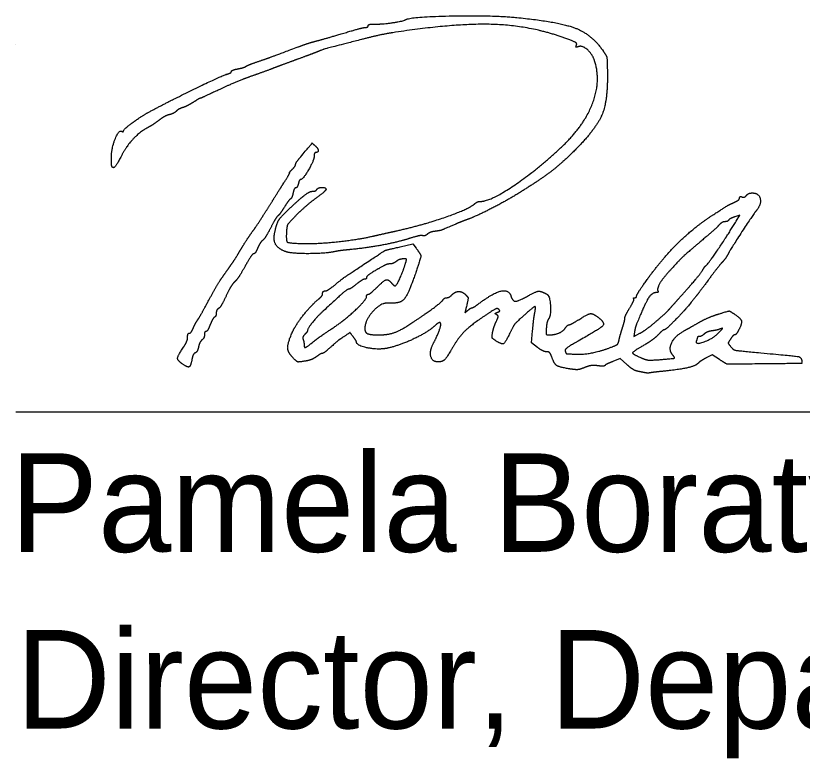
# Model space of a CAD drawing. Extents: x 0 to 40.9, y 0 to 22.
# Drawn here: x 25 to 26.118, y 5.49 to 6.545 of the extents above; entities that cross this region are included whole.
import ezdxf

# ---------------------------------------------------------------- set-up
doc = ezdxf.new("R2010")
doc.units = 0
doc.layers.add('SH_Border', color=7, linetype='Continuous')
doc.layers.add('SH_Cut_Line', color=7, linetype='Continuous')

msp = doc.modelspace()

# ---------------------------------------------------------------- linework, layer by layer
at = {"layer": 'SH_Border'}
for points in [[(26.024, 6.2528), (26.0294, 6.2617), (26.0221, 6.2592)], [(25.5467, 6.2166), (25.5647, 6.2207), (25.5694, 6.2145)], [(25.7417, 6.0738), (25.7334, 6.0802), (25.7348, 6.0972)], [(25.8797, 6.0958), (25.8787, 6.0893), (25.8873, 6.0938)], [(26.0005, 6.0565), (25.9899, 6.0633), (25.9815, 6.0588)], [(25.8686, 6.0495), (25.8595, 6.0578), (25.8489, 6.0537)]]:
    msp.add_lwpolyline(points, dxfattribs=at)
for points in [[(25.5541, 6.5392), (25.5609, 6.5434), (25.6779, 6.5457), (25.7123, 6.5423)], [(25.7123, 6.5423), (25.7716, 6.5365), (25.8191, 6.5182), (25.8349, 6.4951)], [(25.4974, 6.5283), (25.4995, 6.5283), (25.5011, 6.5294), (25.5011, 6.5308)], [(25.5011, 6.5308), (25.5011, 6.5321), (25.5052, 6.5331), (25.5101, 6.533)], [(25.5101, 6.533), (25.5197, 6.5327), (25.5507, 6.5371), (25.5541, 6.5392)], [(25.7848, 6.5116), (25.7343, 6.5305), (25.6263, 6.5345), (25.5359, 6.5208)], [(25.4255, 6.5085), (25.4308, 6.5098), (25.4483, 6.5148), (25.4644, 6.5196)], [(25.4644, 6.5196), (25.4805, 6.5244), (25.4953, 6.5283), (25.4974, 6.5283)], [(25.5359, 6.5208), (25.5267, 6.5193), (25.5067, 6.515), (25.4915, 6.5111)], [(25.4015, 6.5006), (25.4095, 6.5036), (25.4203, 6.5071), (25.4255, 6.5085)], [(25.4915, 6.5111), (25.4405, 6.4979), (25.4363, 6.4966), (25.4255, 6.4923)], [(25.7971, 6.5029), (25.7981, 6.5054), (25.7947, 6.5078), (25.7848, 6.5116)], [(25.3451, 6.48), (25.3598, 6.4851), (25.3663, 6.4875), (25.4015, 6.5006)], [(25.7996, 6.5009), (25.7969, 6.4999), (25.7962, 6.5005), (25.7971, 6.5029)], [(25.8229, 6.4809), (25.8197, 6.4907), (25.8052, 6.503), (25.7996, 6.5009)], [(25.4255, 6.4923), (25.4229, 6.4912), (25.4126, 6.4874), (25.4027, 6.4838)], [(25.8349, 6.4951), (25.8399, 6.4879), (25.8408, 6.4835), (25.8411, 6.4657)], [(25.3271, 6.4729), (25.3285, 6.4739), (25.3366, 6.4771), (25.3451, 6.48)], [(25.4027, 6.4838), (25.3928, 6.4802), (25.3777, 6.4746), (25.3691, 6.4714)], [(25.7774, 6.3597), (25.8084, 6.3892), (25.8322, 6.4527), (25.8229, 6.4809)], [(25.3013, 6.4622), (25.3043, 6.4631), (25.3067, 6.4647), (25.3067, 6.4658)], [(25.3067, 6.4658), (25.3067, 6.4668), (25.3108, 6.4685), (25.3157, 6.4694)], [(25.3157, 6.4694), (25.3207, 6.4703), (25.3258, 6.4719), (25.3271, 6.4729)], [(25.3691, 6.4714), (25.3606, 6.4681), (25.3444, 6.4622), (25.3331, 6.4583)], [(25.8411, 6.4657), (25.8419, 6.4249), (25.8258, 6.3852), (25.7964, 6.3553)], [(25.1891, 6.4079), (25.2194, 6.4241), (25.293, 6.4598), (25.3013, 6.4622)], [(25.3331, 6.4583), (25.3219, 6.4543), (25.3016, 6.4457), (25.2879, 6.4392)], [(25.2879, 6.4392), (25.2743, 6.4328), (25.2626, 6.4275), (25.2621, 6.4275)], [(25.2521, 6.4218), (25.2472, 6.4187), (25.2405, 6.4153), (25.2373, 6.4143)], [(25.2621, 6.4275), (25.2615, 6.4275), (25.257, 6.4249), (25.2521, 6.4218)], [(25.1531, 6.3813), (25.1531, 6.3834), (25.1785, 6.4022), (25.1891, 6.4079)], [(25.2281, 6.4092), (25.2263, 6.4073), (25.2219, 6.4052), (25.2184, 6.4043)], [(25.2373, 6.4143), (25.234, 6.4133), (25.2299, 6.411), (25.2281, 6.4092)], [(25.2035, 6.3962), (25.1989, 6.3927), (25.1918, 6.388), (25.1877, 6.3859)], [(25.2184, 6.4043), (25.2148, 6.4035), (25.2082, 6.3998), (25.2035, 6.3962)], [(25.1877, 6.3859), (25.1772, 6.3806), (25.1573, 6.3597), (25.1511, 6.3476)], [(25.136, 6.3434), (25.1361, 6.3566), (25.1467, 6.3832), (25.1508, 6.3806)], [(25.1508, 6.3806), (25.1521, 6.3798), (25.1531, 6.3801), (25.1531, 6.3813)], [(25.4033, 6.3423), (25.4219, 6.3645), (25.4212, 6.3639), (25.4253, 6.3605)], [(25.4253, 6.3605), (25.4296, 6.3569), (25.4305, 6.3507), (25.4267, 6.3507)], [(25.6607, 6.2811), (25.6748, 6.2811), (25.7429, 6.327), (25.7774, 6.3597)], [(25.7964, 6.3553), (25.7778, 6.3364), (25.7454, 6.3115), (25.7149, 6.2927)], [(25.1373, 6.3297), (25.1365, 6.3305), (25.1359, 6.3366), (25.136, 6.3434)], [(25.1511, 6.3476), (25.1445, 6.3347), (25.1392, 6.3278), (25.1373, 6.3297)], [(25.3979, 6.3337), (25.3979, 6.3349), (25.4004, 6.3388), (25.4033, 6.3423)], [(25.4243, 6.3456), (25.4243, 6.34), (25.4084, 6.3123), (25.4052, 6.3123)], [(25.4267, 6.3507), (25.4254, 6.3507), (25.4243, 6.3484), (25.4243, 6.3456)], [(25.3931, 6.3267), (25.3958, 6.3293), (25.3979, 6.3325), (25.3979, 6.3337)], [(25.3804, 6.3062), (25.3859, 6.3148), (25.39, 6.3219), (25.3894, 6.3219)], [(25.3894, 6.3219), (25.3888, 6.3219), (25.3905, 6.324), (25.3931, 6.3267)], [(25.4052, 6.3123), (25.4041, 6.3123), (25.4026, 6.3096), (25.4018, 6.3063)], [(25.3583, 6.2712), (25.3649, 6.2818), (25.3749, 6.2976), (25.3804, 6.3062)], [(25.3895, 6.2713), (25.4052, 6.2859), (25.418, 6.2955), (25.4219, 6.2955)], [(25.3981, 6.3003), (25.3969, 6.3003), (25.3952, 6.297), (25.3943, 6.2931)], [(25.4018, 6.3063), (25.4009, 6.303), (25.3993, 6.3003), (25.3981, 6.3003)], [(25.4219, 6.2955), (25.4244, 6.2955), (25.4271, 6.2965), (25.4279, 6.2979)], [(25.4411, 6.2982), (25.4411, 6.2971), (25.4344, 6.2912), (25.4261, 6.2851)], [(25.4279, 6.2979), (25.4297, 6.3008), (25.4411, 6.3011), (25.4411, 6.2982)], [(25.3905, 6.2845), (25.3892, 6.2837), (25.3854, 6.2786), (25.382, 6.2731)], [(25.3943, 6.2931), (25.3935, 6.2891), (25.3917, 6.2853), (25.3905, 6.2845)], [(25.4261, 6.2851), (25.4179, 6.279), (25.4054, 6.2681), (25.3984, 6.261)], [(25.7149, 6.2927), (25.6957, 6.2808), (25.6544, 6.2598), (25.6403, 6.2547)], [(26.0213, 6.2797), (26.0256, 6.2816), (26.0291, 6.2845), (26.0291, 6.286)], [(26.0291, 6.286), (26.0291, 6.2875), (26.0307, 6.2882), (26.0326, 6.2875)], [(26.0326, 6.2875), (26.0344, 6.2867), (26.0373, 6.2877), (26.0389, 6.2896)], [(26.0389, 6.2896), (26.0404, 6.2915), (26.0441, 6.2931), (26.047, 6.2931)], [(26.047, 6.2931), (26.0565, 6.2931), (26.0602, 6.277), (26.0528, 6.268)], [(25.382, 6.2731), (25.3786, 6.2676), (25.3745, 6.262), (25.3728, 6.2606)], [(25.5407, 6.2391), (25.5777, 6.2473), (25.6439, 6.2702), (25.6525, 6.2777)], [(25.6525, 6.2777), (25.6546, 6.2796), (25.6583, 6.2811), (25.6607, 6.2811)], [(25.9924, 6.2627), (26.0113, 6.2749), (26.0132, 6.276), (26.0213, 6.2797)], [(25.3366, 6.2383), (25.342, 6.2457), (25.3517, 6.2606), (25.3583, 6.2712)], [(25.3682, 6.2367), (25.3709, 6.2497), (25.3771, 6.2597), (25.3895, 6.2713)], [(25.8977, 6.1702), (25.92, 6.201), (25.965, 6.245), (25.9924, 6.2627)], [(26.0528, 6.268), (26.0487, 6.263), (26.0158, 6.2126), (26.0127, 6.2064)], [(25.3728, 6.2606), (25.3711, 6.2593), (25.3665, 6.2517), (25.3625, 6.2437)], [(25.3984, 6.261), (25.3876, 6.25), (25.3855, 6.2464), (25.3849, 6.2381)], [(25.6403, 6.2547), (25.6357, 6.2531), (25.6287, 6.2503), (25.6247, 6.2485)], [(25.9813, 6.1899), (25.9841, 6.1918), (26.0123, 6.2333), (26.024, 6.2528)], [(26.0081, 6.2523), (26.0059, 6.2523), (26.0019, 6.2498), (25.9992, 6.2469)], [(26.0134, 6.2544), (26.0127, 6.2532), (26.0103, 6.2523), (26.0081, 6.2523)], [(26.0221, 6.2592), (26.018, 6.2577), (26.0141, 6.2556), (26.0134, 6.2544)], [(25.3625, 6.2437), (25.3584, 6.2357), (25.3534, 6.2277), (25.3512, 6.2259)], [(25.6247, 6.2485), (25.6076, 6.2411), (25.6028, 6.2394), (25.5961, 6.2386)], [(25.9992, 6.2469), (25.9965, 6.2439), (25.9841, 6.2328), (25.9715, 6.2223)], [(25.3199, 6.2127), (25.3237, 6.2193), (25.3312, 6.2308), (25.3366, 6.2383)], [(25.3835, 6.2098), (25.3731, 6.2137), (25.366, 6.2262), (25.3682, 6.2367)], [(25.3849, 6.2381), (25.3841, 6.2247), (25.3881, 6.2218), (25.4087, 6.2213)], [(25.4087, 6.2213), (25.428, 6.2207), (25.4858, 6.2268), (25.5071, 6.2316)], [(25.5605, 6.2287), (25.5441, 6.2234), (25.499, 6.2149), (25.4752, 6.2126)], [(25.5071, 6.2316), (25.5151, 6.2334), (25.5302, 6.2368), (25.5407, 6.2391)], [(25.5785, 6.2324), (25.5769, 6.233), (25.5688, 6.2313), (25.5605, 6.2287)], [(25.5853, 6.2346), (25.5832, 6.2328), (25.5802, 6.2318), (25.5785, 6.2324)], [(25.5961, 6.2386), (25.5923, 6.2382), (25.5874, 6.2364), (25.5853, 6.2346)], [(25.3512, 6.2259), (25.349, 6.2241), (25.3458, 6.2191), (25.3439, 6.2147)], [(25.9715, 6.2223), (25.9519, 6.2058), (25.9402, 6.1944), (25.9235, 6.1755)], [(25.3068, 6.192), (25.3102, 6.1968), (25.316, 6.2061), (25.3199, 6.2127)], [(25.3382, 6.2067), (25.3369, 6.2067), (25.3315, 6.1988), (25.3262, 6.1891)], [(25.3439, 6.2147), (25.3421, 6.2103), (25.3395, 6.2067), (25.3382, 6.2067)], [(25.4548, 6.21), (25.4411, 6.2069), (25.3916, 6.2068), (25.3835, 6.2098)], [(25.4752, 6.2126), (25.4668, 6.2118), (25.4577, 6.2106), (25.4548, 6.21)], [(25.4927, 6.1902), (25.5244, 6.2112), (25.5258, 6.2119), (25.5467, 6.2166)], [(25.5694, 6.2145), (25.576, 6.2057), (25.5759, 6.2009), (25.5681, 6.1783)], [(26.0127, 6.2064), (26.0109, 6.2029), (26.007, 6.1975), (26.004, 6.1943)], [(25.5409, 6.1958), (25.5383, 6.1939), (25.5344, 6.1923), (25.5322, 6.1923)], [(25.5508, 6.1994), (25.5479, 6.1993), (25.5434, 6.1977), (25.5409, 6.1958)], [(25.5541, 6.1929), (25.5558, 6.1986), (25.5554, 6.1995), (25.5508, 6.1994)], [(25.2933, 6.1728), (25.2974, 6.1786), (25.3035, 6.1873), (25.3068, 6.192)], [(25.3262, 6.1891), (25.3208, 6.1794), (25.3142, 6.1695), (25.3113, 6.1669)], [(25.4535, 6.1623), (25.4672, 6.1734), (25.4653, 6.172), (25.4927, 6.1902)], [(25.5224, 6.1891), (25.508, 6.1812), (25.4987, 6.1748), (25.4987, 6.1728)], [(25.5322, 6.1923), (25.5299, 6.1923), (25.5255, 6.1909), (25.5224, 6.1891)], [(25.5394, 6.1611), (25.5412, 6.1611), (25.5509, 6.1822), (25.5541, 6.1929)], [(25.946, 6.1469), (25.9614, 6.164), (25.9749, 6.1804), (25.9773, 6.1847)], [(25.9773, 6.1847), (25.9785, 6.1869), (25.9803, 6.1892), (25.9813, 6.1899)], [(26.004, 6.1943), (26.0011, 6.191), (25.9922, 6.1797), (25.9843, 6.169)], [(25.2744, 6.1407), (25.2807, 6.1525), (25.2892, 6.167), (25.2933, 6.1728)], [(25.4987, 6.1728), (25.4987, 6.1716), (25.4975, 6.1707), (25.4961, 6.1707)], [(25.5681, 6.1783), (25.5579, 6.1484), (25.5459, 6.1354), (25.5299, 6.1367)], [(25.9235, 6.1755), (25.9177, 6.1689), (25.9114, 6.156), (25.9129, 6.1537)], [(25.3113, 6.1669), (25.3085, 6.1644), (25.303, 6.1552), (25.299, 6.1467)], [(25.4397, 6.1539), (25.4416, 6.1539), (25.4478, 6.1577), (25.4535, 6.1623)], [(25.4843, 6.1635), (25.4793, 6.1595), (25.4743, 6.1563), (25.4732, 6.1563)], [(25.4961, 6.1707), (25.4946, 6.1707), (25.4893, 6.1674), (25.4843, 6.1635)], [(25.5131, 6.1587), (25.5233, 6.1688), (25.5298, 6.1706), (25.5347, 6.1647)], [(25.5347, 6.1647), (25.5364, 6.1627), (25.5385, 6.1611), (25.5394, 6.1611)], [(25.8827, 6.1468), (25.8827, 6.1482), (25.8895, 6.1587), (25.8977, 6.1702)], [(25.9843, 6.169), (25.9764, 6.1584), (25.9687, 6.1482), (25.9672, 6.1464)], [(25.4309, 6.1426), (25.4339, 6.145), (25.4363, 6.1486), (25.4363, 6.1504)], [(25.4363, 6.1504), (25.4363, 6.1523), (25.4379, 6.1539), (25.4397, 6.1539)], [(25.4732, 6.1563), (25.4713, 6.1562), (25.4628, 6.149), (25.4375, 6.1257)], [(25.5011, 6.1491), (25.5025, 6.1491), (25.5079, 6.1534), (25.5131, 6.1587)], [(25.6199, 6.1482), (25.6249, 6.1531), (25.6349, 6.1532), (25.6398, 6.1483)], [(25.6579, 6.1356), (25.6781, 6.1508), (25.7009, 6.1564), (25.7039, 6.1469)], [(25.7276, 6.1466), (25.7396, 6.1532), (25.7468, 6.1539), (25.7551, 6.1493)], [(25.9106, 6.1515), (25.9043, 6.1515), (25.8947, 6.1363), (25.8827, 6.1071)], [(25.9129, 6.1537), (25.9136, 6.1525), (25.9126, 6.1515), (25.9106, 6.1515)], [(25.2589, 6.1131), (25.2611, 6.1164), (25.2681, 6.1288), (25.2744, 6.1407)], [(25.299, 6.1467), (25.2951, 6.1381), (25.2904, 6.1302), (25.2885, 6.1291)], [(25.3928, 6.0944), (25.3973, 6.1049), (25.4206, 6.1343), (25.4309, 6.1426)], [(25.4527, 6.1025), (25.4682, 6.1129), (25.4987, 6.1416), (25.4987, 6.1459)], [(25.4987, 6.1459), (25.4987, 6.1477), (25.4998, 6.1491), (25.5011, 6.1491)], [(25.5647, 6.1094), (25.5833, 6.1218), (25.6057, 6.1384), (25.6075, 6.1412)], [(25.6075, 6.1412), (25.6085, 6.1429), (25.6109, 6.1443), (25.6127, 6.1443)], [(25.6127, 6.1443), (25.6145, 6.1443), (25.6178, 6.146), (25.6199, 6.1482)], [(25.6398, 6.1483), (25.643, 6.1451), (25.6432, 6.1426), (25.6411, 6.1335)], [(25.7039, 6.1469), (25.7063, 6.1393), (25.7144, 6.1392), (25.7276, 6.1466)], [(25.7551, 6.1493), (25.7594, 6.1469), (25.7611, 6.1188), (25.7572, 6.1137)], [(25.873, 6.13), (25.8768, 6.1363), (25.8794, 6.142), (25.8786, 6.1428)], [(25.8786, 6.1428), (25.8778, 6.1436), (25.8784, 6.1443), (25.8799, 6.1443)], [(25.8799, 6.1443), (25.8815, 6.1443), (25.8827, 6.1454), (25.8827, 6.1468)], [(25.9304, 6.1294), (25.9336, 6.133), (25.9406, 6.1408), (25.946, 6.1469)], [(25.9672, 6.1464), (25.9539, 6.13), (25.9494, 6.1248), (25.9375, 6.1126)], [(25.2885, 6.1291), (25.2867, 6.1281), (25.2851, 6.1252), (25.2851, 6.1227)], [(25.5299, 6.1367), (25.5195, 6.1376), (25.4963, 6.1122), (25.4963, 6.1)], [(25.6411, 6.1335), (25.6387, 6.1232), (25.6388, 6.1227), (25.6426, 6.1262)], [(25.6426, 6.1262), (25.6449, 6.1282), (25.6475, 6.1299), (25.6485, 6.1299)], [(25.6485, 6.1299), (25.6495, 6.1299), (25.6537, 6.1324), (25.6579, 6.1356)], [(25.6866, 6.1278), (25.6848, 6.1296), (25.6789, 6.1268), (25.6664, 6.1183)], [(25.6849, 6.1236), (25.6879, 6.1248), (25.6884, 6.126), (25.6866, 6.1278)], [(25.7378, 6.1221), (25.7396, 6.1315), (25.737, 6.1319), (25.7277, 6.1237)], [(25.866, 6.1152), (25.8659, 6.117), (25.8691, 6.1237), (25.873, 6.13)], [(25.9103, 6.1106), (25.9183, 6.1174), (25.9273, 6.1259), (25.9304, 6.1294)], [(25.2826, 6.1166), (25.2813, 6.1158), (25.2784, 6.1108), (25.2764, 6.1057)], [(25.2851, 6.1227), (25.2851, 6.1202), (25.284, 6.1175), (25.2826, 6.1166)], [(25.4375, 6.1257), (25.4284, 6.1174), (25.4147, 6.1003), (25.4147, 6.0973)], [(25.6664, 6.1183), (25.6466, 6.1049), (25.6294, 6.0879), (25.6211, 6.0735)], [(25.6837, 6.1202), (25.6815, 6.1215), (25.6818, 6.1224), (25.6849, 6.1236)], [(25.683, 6.1103), (25.6859, 6.1166), (25.6861, 6.1187), (25.6837, 6.1202)], [(25.7277, 6.1237), (25.7118, 6.1097), (25.708, 6.1053), (25.7025, 6.0939)], [(25.7348, 6.0972), (25.7356, 6.1066), (25.7369, 6.1178), (25.7378, 6.1221)], [(25.8003, 6.1131), (25.8133, 6.1213), (25.8209, 6.1221), (25.8286, 6.116)], [(25.9703, 6.1086), (25.9783, 6.1131), (25.9914, 6.1188), (25.9996, 6.1213)], [(25.9996, 6.1213), (26.0137, 6.1255), (26.0149, 6.1255), (26.0207, 6.1217)], [(26.0207, 6.1217), (26.0304, 6.1154), (26.0328, 6.108), (26.0281, 6.099)], [(25.2521, 6.1005), (25.2536, 6.1041), (25.2567, 6.1098), (25.2589, 6.1131)], [(25.2764, 6.1057), (25.2743, 6.1005), (25.2717, 6.0963), (25.2705, 6.0963)], [(25.5163, 6.0915), (25.5293, 6.0915), (25.5484, 6.0985), (25.5647, 6.1094)], [(25.5967, 6.1052), (25.5871, 6.0961), (25.5484, 6.0773), (25.5299, 6.0729)], [(25.5938, 6.0795), (25.5979, 6.0871), (25.6043, 6.1034), (25.6043, 6.1062)], [(25.6043, 6.1062), (25.6043, 6.1092), (25.6004, 6.1087), (25.5967, 6.1052)], [(25.6779, 6.0947), (25.6787, 6.0988), (25.681, 6.1059), (25.683, 6.1103)], [(25.7572, 6.1137), (25.756, 6.112), (25.7546, 6.1063), (25.7543, 6.1011)], [(25.7812, 6.101), (25.7831, 6.1037), (25.7856, 6.1059), (25.7868, 6.1059)], [(25.7868, 6.1059), (25.788, 6.1059), (25.7941, 6.1091), (25.8003, 6.1131)], [(25.8286, 6.116), (25.8382, 6.1084), (25.8314, 6.1005), (25.7998, 6.0828)], [(25.8624, 6.1011), (25.8644, 6.107), (25.866, 6.1134), (25.866, 6.1152)], [(25.8827, 6.1071), (25.8816, 6.1044), (25.8802, 6.0994), (25.8797, 6.0958)], [(25.8873, 6.0938), (25.892, 6.0962), (25.9024, 6.1038), (25.9103, 6.1106)], [(25.9375, 6.1126), (25.93, 6.1049), (25.923, 6.0987), (25.9219, 6.0987)], [(25.9508, 6.0976), (25.9536, 6.0991), (25.9624, 6.1041), (25.9703, 6.1086)], [(25.2468, 6.0939), (25.2481, 6.0939), (25.2505, 6.0968), (25.2521, 6.1005)], [(25.2705, 6.0963), (25.2693, 6.0963), (25.2683, 6.0942), (25.2683, 6.0918)], [(25.3945, 6.0587), (25.3869, 6.0663), (25.3863, 6.0791), (25.3928, 6.0944)], [(25.4147, 6.0973), (25.4147, 6.0965), (25.4131, 6.0942), (25.411, 6.0922)], [(25.4212, 6.0802), (25.4287, 6.0862), (25.4339, 6.09), (25.4527, 6.1025)], [(25.4797, 6.0889), (25.4753, 6.0947), (25.4752, 6.0947), (25.4685, 6.0903)], [(25.4963, 6.1), (25.4963, 6.0948), (25.5042, 6.0915), (25.5163, 6.0915)], [(25.6825, 6.0831), (25.6776, 6.0864), (25.6768, 6.0884), (25.6779, 6.0947)], [(25.7543, 6.1011), (25.7538, 6.0935), (25.7545, 6.0915), (25.7576, 6.0915)], [(25.7576, 6.0915), (25.7659, 6.0915), (25.7779, 6.0963), (25.7812, 6.101)], [(25.8577, 6.084), (25.8584, 6.0874), (25.8605, 6.0951), (25.8624, 6.1011)], [(25.9219, 6.0987), (25.9208, 6.0987), (25.917, 6.0955), (25.9134, 6.0917)], [(25.9337, 6.0632), (25.9277, 6.0706), (25.9375, 6.0904), (25.9508, 6.0976)], [(25.9677, 6.0833), (25.9652, 6.0768), (25.9907, 6.0858), (25.9991, 6.0944)], [(25.9897, 6.0972), (25.9859, 6.0967), (25.9809, 6.0946), (25.9787, 6.0927)], [(26.0015, 6.0999), (25.9989, 6.0989), (25.9936, 6.0977), (25.9897, 6.0972)], [(25.9991, 6.0944), (26.0046, 6.1), (26.0052, 6.1013), (26.0015, 6.0999)], [(26.0281, 6.099), (26.026, 6.0949), (26.0233, 6.0915), (26.0222, 6.0915)], [(25.2385, 6.074), (25.2417, 6.0787), (25.2443, 6.0851), (25.2443, 6.0882)], [(25.2443, 6.0882), (25.2443, 6.0913), (25.2454, 6.0939), (25.2468, 6.0939)], [(25.2649, 6.0844), (25.263, 6.0828), (25.2607, 6.0783), (25.2599, 6.0743)], [(25.2683, 6.0918), (25.2683, 6.0893), (25.2668, 6.086), (25.2649, 6.0844)], [(25.411, 6.0922), (25.4089, 6.0901), (25.4079, 6.0869), (25.4086, 6.085)], [(25.4086, 6.085), (25.4093, 6.083), (25.4099, 6.0799), (25.4099, 6.0781)], [(25.4685, 6.0903), (25.4602, 6.0849), (25.4577, 6.0829), (25.4465, 6.0729)], [(25.4843, 6.0815), (25.4843, 6.0824), (25.4822, 6.0857), (25.4797, 6.0889)], [(25.7025, 6.0939), (25.6959, 6.0802), (25.691, 6.0776), (25.6825, 6.0831)], [(25.7998, 6.0828), (25.7866, 6.0754), (25.7804, 6.0705), (25.7812, 6.0683)], [(25.845, 6.0734), (25.8538, 6.0767), (25.8567, 6.0792), (25.8577, 6.084)], [(25.9134, 6.0917), (25.9097, 6.0879), (25.9016, 6.0818), (25.8954, 6.0781)], [(25.9691, 6.0881), (25.9691, 6.0875), (25.9685, 6.0854), (25.9677, 6.0833)], [(25.9719, 6.0891), (25.9704, 6.0891), (25.9691, 6.0886), (25.9691, 6.0881)], [(25.9787, 6.0927), (25.9765, 6.0907), (25.9735, 6.0891), (25.9719, 6.0891)], [(26.0163, 6.0857), (26.0128, 6.0803), (26.0128, 6.0794), (26.0166, 6.0747)], [(26.0222, 6.0915), (26.021, 6.0915), (26.0184, 6.0888), (26.0163, 6.0857)], [(25.2368, 6.0503), (25.2298, 6.0551), (25.2303, 6.0619), (25.2385, 6.074)], [(25.2599, 6.0743), (25.259, 6.0704), (25.2569, 6.0666), (25.2551, 6.0659)], [(25.4099, 6.0781), (25.4099, 6.0732), (25.4134, 6.0738), (25.4212, 6.0802)], [(25.4465, 6.0729), (25.4417, 6.0686), (25.4368, 6.0651), (25.4357, 6.0651)], [(25.5299, 6.0729), (25.5171, 6.0698), (25.4845, 6.076), (25.4843, 6.0815)], [(25.6005, 6.0531), (25.5921, 6.0531), (25.5881, 6.0689), (25.5938, 6.0795)], [(25.6211, 6.0735), (25.613, 6.0594), (25.6066, 6.0531), (25.6005, 6.0531)], [(25.7547, 6.0675), (25.7521, 6.0675), (25.7462, 6.0703), (25.7417, 6.0738)], [(25.7951, 6.064), (25.8057, 6.0634), (25.8318, 6.0683), (25.845, 6.0734)], [(25.8954, 6.0781), (25.8774, 6.0677), (25.8764, 6.0644), (25.8893, 6.0589)], [(26.0166, 6.0747), (26.0203, 6.0702), (26.0253, 6.0692), (26.0592, 6.066)], [(25.2551, 6.0659), (25.2534, 6.0653), (25.2513, 6.0611), (25.2505, 6.0567)], [(25.4357, 6.0651), (25.4346, 6.0651), (25.4308, 6.0629), (25.4272, 6.0603)], [(25.7622, 6.0597), (25.7603, 6.0648), (25.7578, 6.0675), (25.7547, 6.0675)], [(25.7812, 6.0683), (25.7825, 6.0649), (25.7832, 6.0647), (25.7951, 6.064)], [(25.9161, 6.0564), (25.9357, 6.058), (25.9374, 6.0587), (25.9337, 6.0632)], [(26.0592, 6.066), (26.1082, 6.0615), (26.1165, 6.06), (26.1174, 6.0552)], [(25.2505, 6.0567), (25.2487, 6.047), (25.2445, 6.045), (25.2368, 6.0503)], [(25.4107, 6.0541), (25.402, 6.0527), (25.3999, 6.0533), (25.3945, 6.0587)], [(25.4272, 6.0603), (25.4237, 6.0577), (25.4162, 6.0549), (25.4107, 6.0541)], [(25.7876, 6.0431), (25.7725, 6.0456), (25.7657, 6.05), (25.7622, 6.0597)], [(25.8489, 6.0537), (25.8431, 6.0514), (25.838, 6.0489), (25.8376, 6.048)], [(25.8833, 6.04), (25.8803, 6.0407), (25.8737, 6.0449), (25.8686, 6.0495)], [(25.8893, 6.0589), (25.8962, 6.056), (25.9026, 6.0554), (25.9161, 6.0564)], [(25.9698, 6.0509), (25.966, 6.0472), (25.9446, 6.0423), (25.9211, 6.0399)], [(25.9815, 6.0588), (25.9769, 6.0563), (25.9716, 6.0528), (25.9698, 6.0509)], [(26.0471, 6.0501), (26.0114, 6.0497), (26.0111, 6.0497), (26.0005, 6.0565)], [(26.1174, 6.0552), (26.1182, 6.0509), (26.1163, 6.0508), (26.0471, 6.0501)], [(25.8087, 6.0451), (25.8017, 6.0423), (25.7961, 6.0418), (25.7876, 6.0431)], [(25.8275, 6.0476), (25.8218, 6.0484), (25.8145, 6.0474), (25.8087, 6.0451)], [(25.8376, 6.048), (25.8372, 6.0471), (25.8327, 6.0469), (25.8275, 6.0476)], [(25.8935, 6.0379), (25.8909, 6.0384), (25.8863, 6.0394), (25.8833, 6.04)], [(25.9211, 6.0399), (25.9126, 6.039), (25.9039, 6.038), (25.9019, 6.0376)], [(25.9019, 6.0376), (25.9, 6.0372), (25.8962, 6.0373), (25.8935, 6.0379)]]:
    msp.add_open_spline(points, degree=2, dxfattribs=at)
at = {"layer": 'SH_Cut_Line'}
for p, q in [((25, 6.5045), (25, 6.5045)), ((25, 5.9823), (28.5, 5.9823))]:
    msp.add_line(p, q, dxfattribs=at)

# ---------------------------------------------------------------- texts
at = {"layer": 'SH_Border'}
for s, p in [('Pamela Boratyn', (24.9922, 5.7833)), ('Director, Department of Transportation', (25, 5.5323))]:
    msp.add_text(s, height=0.14, dxfattribs=at).set_placement(p)

doc.saveas('drawing.dxf')
